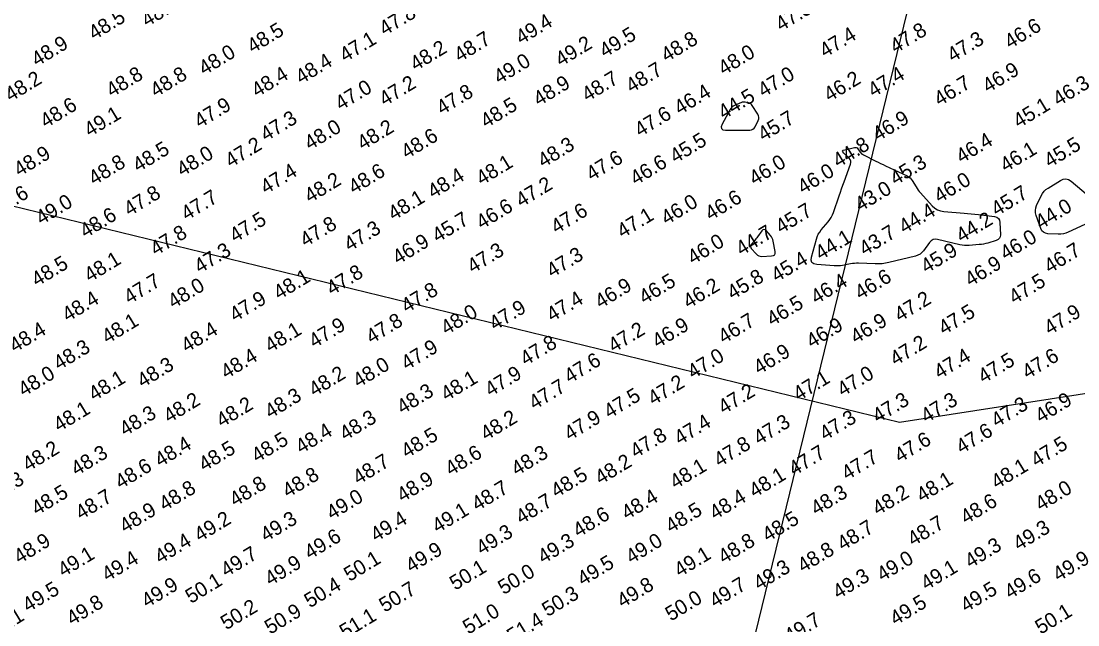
# Model space of a CAD drawing. Extents: x 415488 to 419888, y 1187739 to 1191312.
# Drawn here: x 416796 to 417516, y 1189587 to 1189998 of the extents above; entities that cross this region are included whole.
import ezdxf

# ---------------------------------------------------------------- set-up
doc = ezdxf.new("R2010")
doc.units = 0
for name, color, linetype in [('C-CHAN-POIT', 7, 'Continuous'), ('V-ALGN-TEXT', 7, 'Continuous'), ('V-TOPO-MAJR', 7, 'Continuous'), ('V-TOPO-SOUN', 7, 'Continuous')]:
    doc.layers.add(name, color=color, linetype=linetype)

msp = doc.modelspace()

# ---------------------------------------------------------------- linework, layer by layer
at = {"layer": 'C-CHAN-POIT'}
for p, q in [((416179.26, 1190021.35), (417394.74, 1189724.92)), ((417394.74, 1189724.92), (418985.51, 1189971.03))]:
    msp.add_line(p, q, dxfattribs=at)
at = {"layer": 'V-ALGN-TEXT'}
msp.add_line((417252.51, 1189399.35), (417536.93, 1190565.61), dxfattribs=at)
at = {"layer": 'V-TOPO-MAJR'}
for points in [[(417288.37, 1189943.1), (417287.72, 1189942.98), (417287.08, 1189942.76), (417282.43, 1189940.7), (417281.5, 1189940.2), (417280.69, 1189939.57), (417280, 1189938.81), (417279.43, 1189937.93), (417274.01, 1189927.98), (417273.35, 1189926.26), (417273.53, 1189925.02), (417274.53, 1189924.28), (417276.36, 1189924.04), (417292.92, 1189924.04), (417294.05, 1189924.17), (417295.01, 1189924.58), (417295.8, 1189925.27), (417296.41, 1189926.22), (417298.54, 1189930.6), (417298.92, 1189931.68), (417299.01, 1189932.75), (417298.8, 1189933.8), (417298.3, 1189934.84), (417294.49, 1189940.86), (417294.08, 1189941.4), (417293.6, 1189941.82), (417293.04, 1189942.14), (417292.4, 1189942.36), (417289.7, 1189943), (417289.03, 1189943.1)], [(417462.95, 1189850.24), (417462.07, 1189849.39), (417460.81, 1189848.82), (417455.03, 1189847.04), (417453.58, 1189846.64), (417452.11, 1189846.32), (417450.62, 1189846.08), (417449.12, 1189845.92), (417442.34, 1189845.41), (417440.71, 1189845.34), (417439.09, 1189845.41), (417437.49, 1189845.59), (417435.89, 1189845.9), (417420.75, 1189849.45), (417419.14, 1189849.62), (417417.7, 1189849.34), (417416.42, 1189848.6), (417415.32, 1189847.42), (417411.23, 1189841.77), (417410.12, 1189840.49), (417408.85, 1189839.45), (417407.41, 1189838.67), (417405.8, 1189838.13), (417387.61, 1189833.71), (417385.3, 1189833.23), (417382.98, 1189832.92), (417380.64, 1189832.76), (417378.28, 1189832.77), (417366.85, 1189833.21), (417365.47, 1189833.22), (417364.09, 1189833.16), (417362.72, 1189833.02), (417361.36, 1189832.81), (417355.92, 1189831.8), (417354.55, 1189831.59), (417353.18, 1189831.47), (417351.81, 1189831.43), (417350.43, 1189831.49), (417338.5, 1189832.31), (417336.44, 1189832.76), (417335.15, 1189833.75), (417334.63, 1189835.3), (417334.89, 1189837.39), (417338.21, 1189849.62), (417338.78, 1189851.34), (417339.53, 1189852.97), (417340.45, 1189854.51), (417341.55, 1189855.96), (417346.3, 1189861.55), (417347.41, 1189862.99), (417348.37, 1189864.52), (417349.19, 1189866.13), (417349.85, 1189867.83), (417353.72, 1189879.24), (417354.55, 1189881.64), (417355.38, 1189884.03), (417356.24, 1189886.41), (417357.11, 1189888.79), (417361.49, 1189900.68), (417361.76, 1189901.83), (417361.69, 1189902.9), (417361.28, 1189903.89), (417360.53, 1189904.81), (417356.87, 1189908.31), (417356.22, 1189909.11), (417356.11, 1189909.76), (417356.54, 1189910.27), (417357.5, 1189910.63), (417364.09, 1189912.16), (417364.77, 1189912.23), (417365.37, 1189912.11), (417365.91, 1189911.8), (417366.37, 1189911.31), (417368.08, 1189908.95), (417368.54, 1189908.39), (417369.05, 1189907.9), (417369.62, 1189907.48), (417370.24, 1189907.12), (417378.72, 1189902.89), (417380.35, 1189902.08), (417381.98, 1189901.28), (417383.62, 1189900.48), (417385.27, 1189899.7), (417399.97, 1189892.77), (417401.05, 1189892.17), (417402, 1189891.43), (417402.83, 1189890.55), (417403.53, 1189889.54), (417406.09, 1189885.21), (417406.76, 1189884.15), (417407.48, 1189883.12), (417408.25, 1189882.14), (417409.07, 1189881.2), (417417.11, 1189872.45), (417418.83, 1189870.88), (417420.74, 1189869.7), (417422.84, 1189868.92), (417425.14, 1189868.53), (417438.81, 1189867.43), (417441.25, 1189867.22), (417443.69, 1189866.99), (417446.13, 1189866.73), (417448.57, 1189866.44), (417459.46, 1189865.1), (417461.09, 1189864.67), (417462.28, 1189863.83), (417463.01, 1189862.57), (417463.3, 1189860.91), (417463.59, 1189852.72), (417463.46, 1189851.35)], [(417308.18, 1189850.41), (417307.64, 1189851.34), (417306.95, 1189852.19), (417303.94, 1189855.48), (417303.2, 1189856.09), (417302.48, 1189856.27), (417301.78, 1189856.02), (417301.11, 1189855.33), (417298.04, 1189851.19), (417297.54, 1189850.52), (417297.03, 1189849.85), (417296.5, 1189849.19), (417295.97, 1189848.54), (417293.82, 1189845.96), (417293.42, 1189845.31), (417293.29, 1189844.67), (417293.43, 1189844.04), (417293.85, 1189843.4), (417297.23, 1189839.56), (417298.02, 1189838.82), (417298.92, 1189838.31), (417299.9, 1189838.02), (417300.99, 1189837.95), (417307.67, 1189838.21), (417308.94, 1189838.45), (417309.78, 1189839.04), (417310.17, 1189839.98), (417310.13, 1189841.27), (417308.85, 1189848.35), (417308.59, 1189849.41)]]:
    msp.add_lwpolyline(points, close=True, dxfattribs=at)
msp.add_lwpolyline([(417532.5, 1189864.97), (417509.81, 1189854.42), (417508.18, 1189853.78), (417506.5, 1189853.34), (417504.79, 1189853.1), (417503.03, 1189853.07), (417495.92, 1189853.38), (417494.29, 1189853.65), (417492.96, 1189854.33), (417491.92, 1189855.4), (417491.17, 1189856.88), (417487.96, 1189865.89), (417487.51, 1189867.6), (417487.42, 1189869.3), (417487.68, 1189870.99), (417488.28, 1189872.65), (417491.39, 1189879.29), (417492.26, 1189880.86), (417493.33, 1189882.26), (417494.6, 1189883.47), (417496.07, 1189884.52), (417504.51, 1189889.69), (417506.41, 1189890.54), (417508.27, 1189890.73), (417510.07, 1189890.26), (417511.83, 1189889.14), (417529.23, 1189874.49)], dxfattribs=at)

# ---------------------------------------------------------------- texts
at = {"layer": 'V-TOPO-SOUN'}
for s, p in [('48.4 ', (416882.1, 1189993.99)), ('48.5 ', (416846.08, 1189984.97)), ('47.8 ', (417044.08, 1189987.99)), ('47.3 ', (417314.09, 1189990.98)), ('49.4 ', (417137.09, 1189981.99)), ('46.6 ', (417470.09, 1189978.97)), ('48.5 ', (416954.09, 1189975.98)), ('47.1 ', (417017.11, 1189969.98)), ('48.7 ', (417095.1, 1189969.98)), ('49.5 ', (417194.08, 1189973)), ('48.8 ', (417236.11, 1189969.98)), ('47.4 ', (417344.08, 1189973)), ('47.8 ', (417392.11, 1189975.98)), ('47.3 ', (417431.09, 1189969.98)), ('48.9 ', (416807.1, 1189966.99)), ('48.2 ', (417065.11, 1189963.97)), ('49.2 ', (417164.09, 1189966.99)), ('48.0 ', (416921.08, 1189960.99)), ('48.4 ', (416987.09, 1189954.98)), ('49.0 ', (417122.1, 1189954.98)), ('48.0 ', (417275.08, 1189960.99)), ('48.7 ', (417212.09, 1189948.98)), ('46.9 ', (417455.1, 1189948.98)), ('48.2 ', (416789.09, 1189942.98)), ('48.8 ', (416858.09, 1189946)), ('48.8 ', (416888.11, 1189946)), ('48.4 ', (416957.1, 1189946)), ('48.7 ', (417182.1, 1189942.98)), ('47.0 ', (417302.08, 1189946)), ('46.2 ', (417347.1, 1189942.98)), ('47.4 ', (417377.08, 1189946)), ('46.7 ', (417422.1, 1189939.99)), ('47.0 ', (417014.09, 1189936.97)), ('47.2 ', (417044.08, 1189939.99)), ('47.8 ', (417083.09, 1189933.99)), ('48.9 ', (417149.1, 1189939.99)), ('46.4 ', (417245.09, 1189933.99)), ('46.3 ', (417503.1, 1189939.99)), ('44.5 ', (417275.08, 1189930.97)), ('48.6 ', (416813.11, 1189925)), ('47.9 ', (416918.09, 1189925)), ('48.5 ', (417113.11, 1189925)), ('47.6 ', (417218.09, 1189918.99)), ('45.1 ', (417476.1, 1189925)), ('49.1 ', (416843.09, 1189918.99)), ('47.3 ', (416963.11, 1189915.98)), ('45.7 ', (417302.08, 1189915.98)), ('46.9 ', (417380.1, 1189915.98)), ('48.0 ', (416993.09, 1189909.97)), ('48.2 ', (417029.08, 1189909.97)), ('47.2 ', (416939.09, 1189898)), ('48.6 ', (417059.1, 1189903.97)), ('48.3 ', (417152.08, 1189898)), ('45.5 ', (417242.11, 1189900.98)), ('44.8 ', (417353.1, 1189898)), ('46.4 ', (417437.09, 1189900.98)), ('45.5 ', (417497.1, 1189898)), ('48.9 ', (416795.1, 1189891.99)), ('48.5 ', (416876.1, 1189894.98)), ('48.0 ', (416906.09, 1189891.99)), ('46.1 ', (417467.11, 1189894.98)), ('48.8 ', (416846.08, 1189885.99)), ('48.1 ', (417110.09, 1189885.99)), ('47.6 ', (417185.09, 1189888.97)), ('46.6 ', (417215.11, 1189885.99)), ('46.0 ', (417296.08, 1189885.99)), ('45.3 ', (417392.11, 1189885.99)), ('47.4 ', (416963.11, 1189879.98)), ('48.6 ', (417023.08, 1189879.98)), ('48.4 ', (417077.08, 1189876.97)), ('46.0 ', (417329.08, 1189879.98)), ('48.2 ', (416993.09, 1189873.98)), ('47.2 ', (417137.09, 1189871)), ('46.0 ', (417422.1, 1189873.98)), ('48.6 ', (416780.1, 1189864.99)), ('47.8 ', (416870.1, 1189864.99)), ('47.7 ', (416909.1, 1189861.97)), ('48.1 ', (417050.08, 1189861.97)), ('46.6 ', (417266.09, 1189861.97)), ('43.0 ', (417368.09, 1189867.98)), ('45.7 ', (417461.11, 1189864.99)), ('49.0 ', (416810.09, 1189858.99)), ('46.6 ', (417110.09, 1189855.97)), ('46.0 ', (417236.11, 1189858.99)), ('44.0 ', (417491.09, 1189855.97)), ('48.6 ', (416840.11, 1189850)), ('47.5 ', (416942.11, 1189846.98)), ('45.7 ', (417080.1, 1189846.98)), ('47.6 ', (417161.11, 1189852.98)), ('47.1 ', (417206.09, 1189850)), ('45.7 ', (417314.09, 1189852.98)), ('44.4 ', (417398.08, 1189852.98)), ('47.8 ', (416990.11, 1189843.99)), ('47.3 ', (417020.1, 1189840.98)), ('44.2 ', (417437.09, 1189846.98)), ('47.8 ', (416888.11, 1189837.99)), ('44.7 ', (417287.09, 1189837.99)), ('44.1 ', (417341.09, 1189834.97)), ('43.7 ', (417371.08, 1189837.99)), ('46.0 ', (417467.11, 1189834.97)), ('47.3 ', (416918.09, 1189825.98)), ('46.9 ', (417053.1, 1189831.99)), ('47.3 ', (417104.08, 1189825.98)), ('46.0 ', (417254.08, 1189831.99)), ('45.9 ', (417413.11, 1189825.98)), ('46.7 ', (417497.1, 1189825.98)), ('48.1 ', (416843.09, 1189819.98)), ('47.3 ', (417158.09, 1189823)), ('45.4 ', (417311.11, 1189819.98)), ('48.5 ', (416807.1, 1189816.99)), ('46.9 ', (417443.09, 1189816.99)), ('47.7 ', (416870.1, 1189804.98)), ('48.1 ', (416972.1, 1189807.97)), ('47.8 ', (417008.09, 1189810.99)), ('46.5 ', (417221.08, 1189804.98)), ('45.8 ', (417281.09, 1189807.97)), ('46.4 ', (417338.11, 1189804.98)), ('46.6 ', (417368.09, 1189807.97)), ('47.5 ', (417473.08, 1189804.98)), ('48.0 ', (416900.08, 1189801.97)), ('47.8 ', (417059.1, 1189798.98)), ('46.9 ', (417191.09, 1189801.97)), ('46.2 ', (417251.1, 1189801.97)), ('48.4 ', (416828.1, 1189792.98)), ('47.9 ', (416942.11, 1189792.98)), ('47.4 ', (417158.09, 1189792.98)), ('46.5 ', (417308.09, 1189789.99)), ('47.2 ', (417395.09, 1189792.98)), ('48.0 ', (417086.11, 1189783.99)), ('47.9 ', (417119.08, 1189786.97)), ('47.5 ', (417425.08, 1189783.99)), ('47.9 ', (417497.1, 1189783.99)), ('48.1 ', (416855.1, 1189777.98)), ('47.9 ', (416996.08, 1189775)), ('47.8 ', (417035.09, 1189777.98)), ('46.9 ', (417230.1, 1189775)), ('46.7 ', (417275.08, 1189777.98)), ('46.9 ', (417335.09, 1189775)), ('46.9 ', (417365.11, 1189777.98)), ('48.4 ', (416792.08, 1189771.98)), ('48.4 ', (416909.1, 1189771.98)), ('48.1 ', (416966.09, 1189771.98)), ('47.2 ', (417200.08, 1189771.98)), ('47.8 ', (417140.11, 1189762.99)), ('47.2 ', (417392.11, 1189762.99)), ('48.3 ', (416822.1, 1189759.97)), ('48.4 ', (416936.11, 1189753.97)), ('47.9 ', (417059.1, 1189759.97)), ('47.0 ', (417254.08, 1189753.97)), ('46.9 ', (417299.1, 1189756.99)), ('47.4 ', (417422.1, 1189753.97)), ('47.6 ', (417482.1, 1189753.97)), ('48.3 ', (416879.09, 1189748)), ('48.0 ', (417026.1, 1189748)), ('47.6 ', (417170.1, 1189750.98)), ('47.5 ', (417452.08, 1189750.98)), ('48.0 ', (416798.08, 1189741.99)), ('48.2 ', (416996.08, 1189741.99)), ('47.9 ', (417116.09, 1189741.99)), ('47.0 ', (417356.09, 1189741.99)), ('48.1 ', (416846.08, 1189738.97)), ('48.1 ', (417086.11, 1189738.97)), ('47.7 ', (417146.08, 1189732.97)), ('47.2 ', (417227.08, 1189735.99)), ('47.1 ', (417326.1, 1189738.97)), ('48.3 ', (416966.09, 1189726.97)), ('48.3 ', (417056.09, 1189729.99)), ('47.5 ', (417197.1, 1189726.97)), ('47.2 ', (417275.08, 1189729.99)), ('48.1 ', (416822.1, 1189717.98)), ('48.2 ', (416897.1, 1189723.98)), ('48.2 ', (416933.09, 1189721)), ('47.3 ', (417380.1, 1189723.98)), ('47.3 ', (417413.11, 1189723.98)), ('47.3 ', (417461.11, 1189721)), ('46.9 ', (417491.09, 1189723.98)), ('48.3 ', (416867.11, 1189714.99)), ('48.3 ', (417017.11, 1189711.97)), ('48.2 ', (417113.11, 1189711.97)), ('47.9 ', (417170.1, 1189711.97)), ('47.3 ', (417344.08, 1189711.97)), ('48.4 ', (416987.09, 1189702.98)), ('47.4 ', (417245.09, 1189708.99)), ('47.3 ', (417299.1, 1189708.99)), ('47.6 ', (417437.09, 1189702.98)), ('48.5 ', (416957.1, 1189696.98)), ('48.5 ', (417059.1, 1189700)), ('47.8 ', (417215.11, 1189700)), ('47.6 ', (417395.09, 1189696.98)), ('48.2 ', (416801.1, 1189690.98)), ('48.4 ', (416891.09, 1189693.99)), ('48.5 ', (416921.08, 1189690.98)), ('47.8 ', (417272.1, 1189693.99)), ('47.7 ', (417323.08, 1189687.99)), ('47.5 ', (417488.11, 1189693.99)), ('48.3 ', (416834.1, 1189687.99)), ('48.7 ', (417026.1, 1189681.99)), ('48.6 ', (417089.09, 1189687.99)), ('48.3 ', (417134.1, 1189687.99)), ('48.2 ', (417191.09, 1189681.99)), ('47.7 ', (417359.1, 1189684.97)), ('48.6 ', (416864.09, 1189678.97)), ('48.1 ', (417242.11, 1189678.97)), ('48.1 ', (417461.11, 1189678.97)), ('48.3 ', (416777.08, 1189669.98)), ('48.8 ', (416978.1, 1189673)), ('48.9 ', (417056.09, 1189669.98)), ('48.5 ', (417161.11, 1189673)), ('48.1 ', (417296.08, 1189673)), ('48.1 ', (417410.09, 1189669.98)), ('48.5 ', (416807.1, 1189660.99)), ('48.8 ', (416894.08, 1189663.97)), ('48.8 ', (416942.11, 1189666.99)), ('48.7 ', (417107.1, 1189663.97)), ('48.3 ', (417338.11, 1189660.99)), ('48.2 ', (417380.1, 1189660.99)), ('48.0 ', (417491.09, 1189663.97)), ('48.7 ', (416837.09, 1189657.97)), ('49.0 ', (417008.09, 1189657.97)), ('48.7 ', (417137.09, 1189654.99)), ('48.4 ', (417209.1, 1189657.97)), ('48.4 ', (417269.08, 1189657.97)), ('48.6 ', (417440.11, 1189654.99)), ('48.9 ', (416867.11, 1189648.98)), ('49.1 ', (417080.1, 1189648.98)), ('48.6 ', (417176.1, 1189646)), ('48.5 ', (417239.09, 1189648.98)), ('49.2 ', (416918.09, 1189642.98)), ('49.3 ', (416963.11, 1189642.98)), ('49.4 ', (417038.11, 1189642.98)), ('48.5 ', (417305.1, 1189642.98)), ('48.7 ', (417404.08, 1189639.99)), ('49.6 ', (416993.09, 1189630.97)), ('49.3 ', (417110.09, 1189633.99)), ('48.7 ', (417356.09, 1189636.97)), ('49.3 ', (417476.1, 1189636.97)), ('48.9 ', (416795.1, 1189627.98)), ('49.4 ', (416891.09, 1189627.98)), ('49.3 ', (417152.08, 1189627.98)), ('49.0 ', (417212.09, 1189627.98)), ('48.8 ', (417275.08, 1189627.98)), ('49.3 ', (417443.09, 1189625)), ('49.1 ', (416825.08, 1189618.99)), ('49.7 ', (416936.11, 1189618.99)), ('49.9 ', (417062.09, 1189621.98)), ('49.1 ', (417245.09, 1189618.99)), ('48.8 ', (417329.08, 1189621.98)), ('49.4 ', (416855.1, 1189615.98)), ('49.9 ', (416966.09, 1189612.99)), ('50.1 ', (417020.1, 1189615.98)), ('50.1 ', (417092.11, 1189609.97)), ('49.5 ', (417179.08, 1189612.99)), ('49.3 ', (417299.1, 1189609.97)), ('49.0 ', (417383.09, 1189615.98)), ('49.1 ', (417413.11, 1189609.97)), ('49.9 ', (417503.1, 1189615.98)), ('50.0 ', (417125.08, 1189606.99)), ('49.3 ', (417353.1, 1189603.97)), ('49.6 ', (417470.09, 1189603.97)), ('49.5 ', (416801.1, 1189594.98)), ('49.9 ', (416882.1, 1189598)), ('50.1 ', (416912.09, 1189600.98)), ('50.4 ', (416993.09, 1189598)), ('50.7 ', (417044.08, 1189594.98)), ('49.8 ', (417206.09, 1189598)), ('49.7 ', (417269.08, 1189598)), ('49.5 ', (417440.11, 1189594.98)), ('50.3 ', (417155.1, 1189591.99)), ('50.0 ', (417239.09, 1189588.97)), ('49.8 ', (416831.09, 1189585.99)), ('50.2 ', (416936.11, 1189582.97)), ('49.5 ', (417392.11, 1189585.99)), ('49.1 ', (416777.08, 1189576.97)), ('50.9 ', (416966.09, 1189579.99)), ('51.1 ', (417017.11, 1189576.97)), ('51.0 ', (417101.1, 1189579.99)), ('51.4 ', (417131.09, 1189573.98)), ('49.7 ', (417320.09, 1189573.98)), ('50.1 ', (417491.09, 1189579.99))]:
    msp.add_text(s, height=9.996, rotation=31.2939, dxfattribs=at).set_placement(p)

doc.saveas('drawing.dxf')
